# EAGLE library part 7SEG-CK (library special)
7-segment DISPLAY single cathode, 13 mm
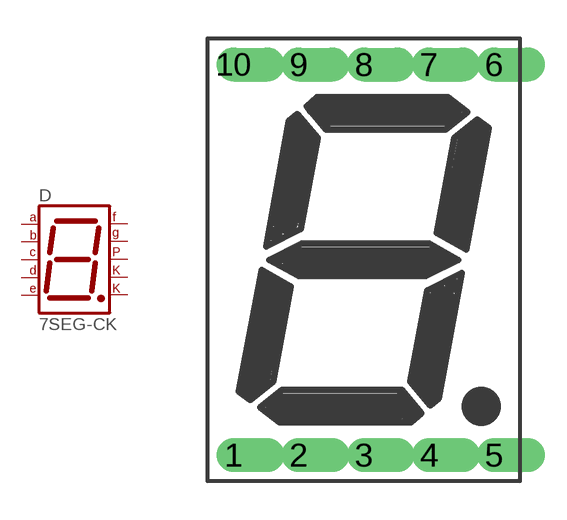
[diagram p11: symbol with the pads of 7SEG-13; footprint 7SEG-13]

Designator prefix D

## 7SEG-CK  [7SEG-13]
1  E  pas
2  D  pas
3  CK1  pas
4  C  pas
5  DP  pas
6  B  pas
7  A  pas
8  CK2  pas
9  F  pas
10  G  pas

## Footprint 7SEG-13 (pad centres in mm)
7-segment DISPLAY 13 mm
drill 0.813 offset: 1 -5.08,-7.62; 2 -2.54,-7.62; 3 0,-7.62; 4 2.54,-7.62; 5 5.08,-7.62; 6 5.08,7.62; 7 2.54,7.62; 8 0,7.62; 9 -2.54,7.62; 10 -5.08,7.62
